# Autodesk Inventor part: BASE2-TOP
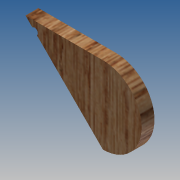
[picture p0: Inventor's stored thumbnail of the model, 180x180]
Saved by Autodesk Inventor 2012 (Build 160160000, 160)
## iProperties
Created: 2011-01
Part Number: BASE2-TOP
Document SubType Name: Modeling
Designer: Microsoft
Density: 1 g/cm^3
Material: Default
Author: Microsoft
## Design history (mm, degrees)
sketch "Sketch1"
  geometry: L1 (9.525, 0)-(9.525, 19.05); L2 (-9.525, 19.05)-(-9.525, 0); L3 (-9.525, 19.05)-(9.525, 0); A1 r 9.525 centre (0, 0) between (-9.525, 0) and (9.525, 0); A2 r 9.525 centre (0, 19.05) between (9.525, 19.05) and (-9.525, 19.05); 1 further point
  constraints: 6 end point, 4 point on circle, 3 tangent, 2 centre point, 1 coincident, 1 vertical alignment
  dimensions: "d3" = 9.525 radius of A2; "d4" = 9.525 radius of A1; "d5" = 19.05 distance of L1.start L1.end; "d6" = 19.05 distance of point (0, 0) A2.centre
extrude "Extrusion1" new body sketch "Sketch1" distance "d7" = 12.7; taper "d8" = 0 deg
sketch "Sketch2"
  geometry: L1 (13.47, 0)-(13.47, 12.7) reference; L2 (0, 0)-(26.941, 0) reference; C1 r 0.794 at (13.47, 6.35); 1 further point
  constraints: 1 centre point, 1 midpoint
  dimensions: "d31" = 1.5875 diameter of C1; "d32" = 6.35 distance from line of L2 C1.centre
extrude "Extrusion2" cut sketch "Sketch2" distance "d10" = 6.35; taper "d11" = 0 deg
sketch "Sketch3"
  geometry: C1 r 1.587 at (0, -3.175); C2 r 0.794 at (0, -3.175) reference; 1 further point
  constraints: 1 centre point, 1 concentric
  dimensions: "d12" = 3.175 diameter of C1
extrude "Extrusion3" cut sketch "Sketch3" distance "d13" = 1.5875; taper "d14" = 0 deg
workplane "Work Plane1"
sketch "Sketch5"
  geometry: L1 (-9.525, 19.05)-(-8.622, 19.953); L2 (9.525, 0)-(-9.525, 19.05) reference; C1 r 0.794 at (-7.28, 16.805); 1 further point
  constraints: 2 end point, 1 centre point, 1 perpendicular, 1 point on line
  dimensions: "d21" = 1.5875 diameter of C1; "d22" = 3.175 distance from line of L1 C1.centre
extrude "Extrusion4" cut sketch "Sketch5" distance "d23" = 3.175; taper "d24" = 0 deg
sketch "Sketch6"
  geometry: C1 r 1.588 at (-7.28, -16.805); A1 r 0.794 centre (-7.28, -16.805) between (-6.719, -16.244) and (-7.841, -17.366) reference; 1 further point
  constraints: 1 centre point, 1 coincident
  dimensions: "d25" = 3.175 diameter of C1
extrude "Extrusion5" cut sketch "Sketch6" distance "d26" = 1.5875; taper "d27" = 0 deg
fillet "Fillet1" dims "d30" = 2.54
sketch "Sketch8"
  geometry: L1 (-9.525, 19.05)-(9.525, 0) reference; L2 (-9.525, 0)-(-9.525, 19.05) reference; A1 r 9.525 centre (0, 0) between (-9.525, 0) and (9.525, 0) reference
extrude "Extrusion7" cut sketch "Sketch8" distance "d33" = 3.175; taper "d34" = 0 deg
sketch "Sketch9"
  geometry: L1 (7.841, -17.366)-(6.719, -16.244) reference; C1 r 1.588 at (7.28, -16.805); A1 r 0.794 centre (7.28, -16.805) between (6.719, -16.244) and (7.841, -17.366) reference; 1 further point
  constraints: 1 centre point, 1 coincident
  dimensions: "d37" = 3.175 diameter of C1
extrude "Extrusion8" cut sketch "Sketch9" distance "d35" = 0.79375; taper "d36" = 0 deg
sketch "Sketch10"
  geometry: L1 (-6.719, 16.244)-(9.525, 0) reference; L2 (-9.525, 19.05)-(-7.841, 17.366) reference; L3 (-9.525, 0)-(-9.525, 19.05) reference; A1 r 0.794 centre (-7.28, 16.805) between (-7.841, 17.366) and (-6.719, 16.244) reference; A2 r 9.525 centre (0, 0) between (-9.525, 0) and (9.525, 0) reference
extrude "Extrusion9" sketch "Sketch10" distance "d38" = 3.175; taper "d39" = 0 deg
mirror "Mirror1"
body "Solid1"
other parameters: "d17" = -6.35
